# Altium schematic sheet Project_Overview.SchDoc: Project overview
size A4; Date: Not used; ApprovedBy: Not used; CheckedBy: Not used; Author: Not used; CompanyName: STMicroelectronics; DrawnBy: Not used; Engineer: Not used; Organization: Not used; Address1: Not used; Address2: Not used; Address3: Not used; Address4: Not used; DocumentNumber: Not used; Revision: Not used; SheetNumber: 1; SheetTotal: 12
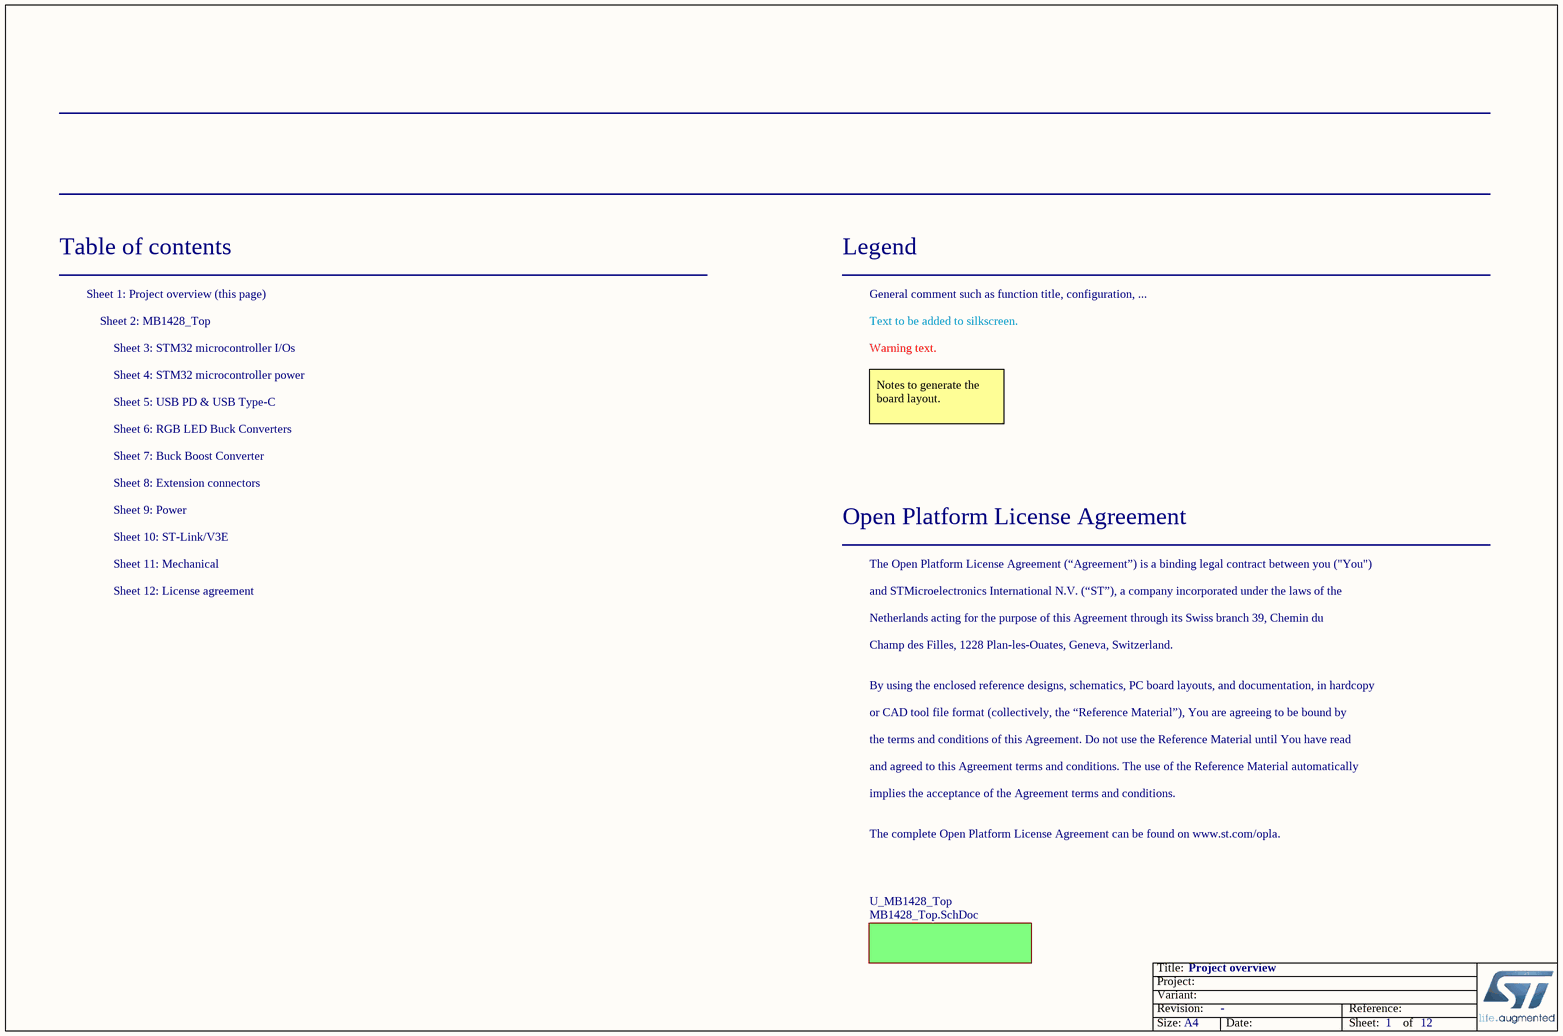
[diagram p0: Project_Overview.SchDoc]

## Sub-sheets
U_MB1428_Top = MB1428_Top.SchDoc: no entries

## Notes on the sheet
- Table of contents
- Sheet 1: Project overview (this page)
- Legend
- General comment such as function title, configuration, ...
- Sheet 2: MB1428_Top
- Sheet 3: STM32 microcontroller I/Os
- Sheet 4: STM32 microcontroller power
- Text to be added to silkscreen.
- Warning text.
- Sheet 6: RGB LED Buck Converters
- Sheet 5: USB PD & USB Type-C
- Notes to generate the board layout.
- Sheet 9: Power
- Sheet 8: Extension connectors
- Sheet 7: Buck Boost Converter
- Sheet 10: ST-Link/V3E
- Sheet 11: Mechanical
- Open Platform License Agreement
- The Open Platform License Agreement (“Agreement”) is a binding legal contract between you ("You")
- Sheet 12: License agreement
- and STMicroelectronics International N.V. (“ST”), a company incorporated under the laws of the
- Netherlands acting for the purpose of this Agreement through its Swiss branch 39, Chemin du
- Champ des Filles, 1228 Plan-les-Ouates, Geneva, Switzerland.
- By using the enclosed reference designs, schematics, PC board layouts, and documentation, in hardcopy
- or CAD tool file format (collectively, the “Reference Material”), You are agreeing to be bound by
- the terms and conditions of this Agreement. Do not use the Reference Material until You have read
- and agreed to this Agreement terms and conditions. The use of the Reference Material automatically
- implies the acceptance of the Agreement terms and conditions.
- The complete Open Platform License Agreement can be found on www.st.com/opla.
